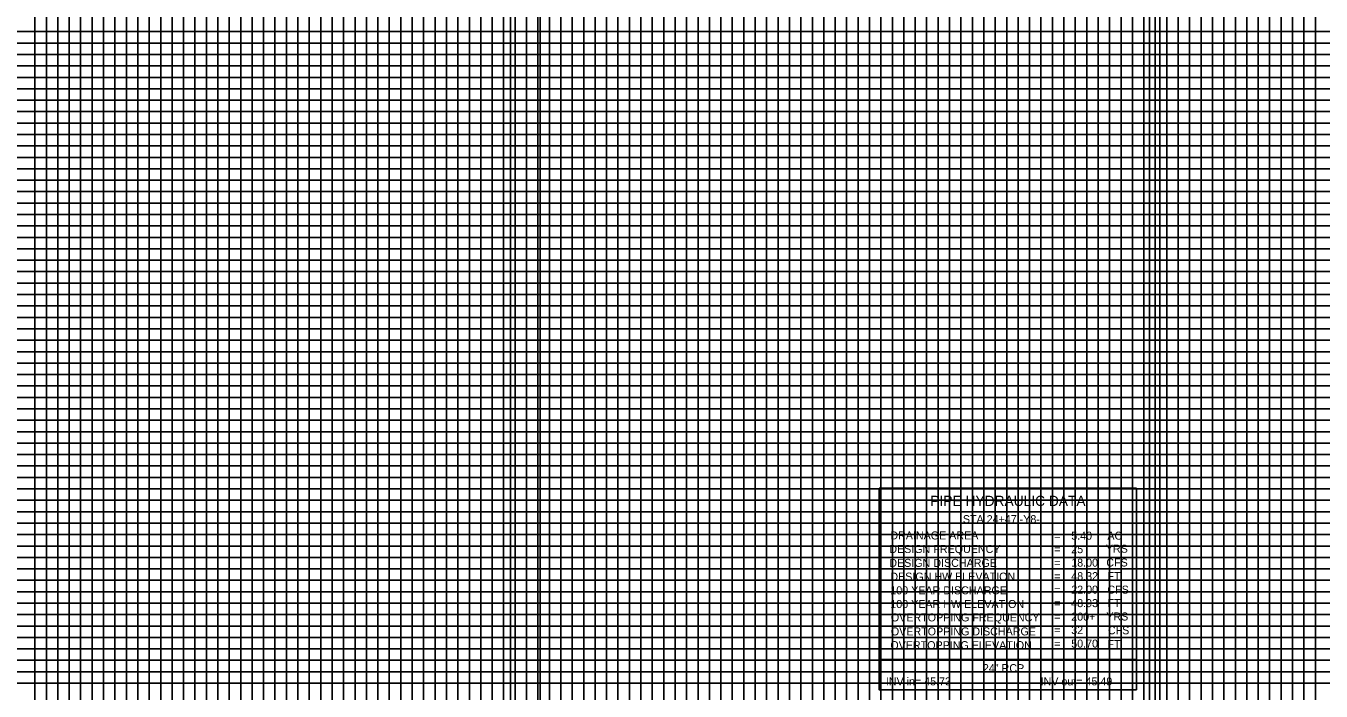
# Model space of a CAD drawing. Extents: x 2345490 to 2445302, y 465165 to 573888.
# Drawn here: x 2382738 to 2383304, y 541266 to 541557 of the extents above; entities that cross this region are included whole.
import ezdxf

# ---------------------------------------------------------------- set-up
doc = ezdxf.new("R2010")
doc.units = 0
for name, color, linetype in [('Old_Level_18', 7, 'Continuous'), ('Old_Level_4', 7, 'Continuous'), ('Old_Level_41', 7, 'Continuous'), ('Old_Level_42', 7, 'Continuous'), ('Old_Level_43', 7, 'Continuous'), ('Old_Level_50', 7, 'Continuous'), ('Old_Level_51', 7, 'Continuous')]:
    doc.layers.add(name, color=color, linetype=linetype)

msp = doc.modelspace()

# ---------------------------------------------------------------- linework, layer by layer
at = {"layer": 'Old_Level_18'}
for points in [[(2383216.79875, 542049.5045), (2381716.79875, 542049.5045), (2381716.79875, 540999.5045), (2383216.79875, 540999.5045)], [(2384616.79875, 542049.5045), (2383116.79875, 542049.5045), (2383116.79875, 540999.5045), (2384616.79875, 540999.5045)]]:
    msp.add_lwpolyline(points, close=True, dxfattribs=at)
at = {"layer": 'Old_Level_4'}
for p, q in [((2383111.01452, 541354.8205), (2383223.51452, 541354.8205)), ((2383111.01452, 541279.8205), (2383111.01452, 541354.8205)), ((2383223.51452, 541354.8205), (2383223.51452, 541279.8205)), ((2383223.51452, 541279.8205), (2383111.01452, 541279.8205))]:
    msp.add_line(p, q, dxfattribs=at)
msp.add_lwpolyline([(2383111.01452, 541279.8205), (2383223.51452, 541279.8205), (2383223.51452, 541266.6055), (2383111.01452, 541266.6055)], close=True, dxfattribs=at)
at = {"layer": 'Old_Level_41'}
for points in [[(2382691.79875, 542049.5045), (2382741.79875, 542049.5045), (2382741.79875, 541024.5045), (2382791.79875, 541024.5045), (2382791.79875, 542049.5045), (2382841.79875, 542049.5045), (2382841.79875, 541024.5045), (2382891.79875, 541024.5045), (2382891.79875, 542049.5045), (2382941.79875, 542049.5045), (2382941.79875, 541024.5045), (2382991.79875, 541024.5045), (2382991.79875, 542049.5045)], [(2382716.79875, 542049.5045), (2382766.79875, 542049.5045), (2382766.79875, 541024.5045), (2382816.79875, 541024.5045), (2382816.79875, 542049.5045), (2382866.79875, 542049.5045), (2382866.79875, 541024.5045), (2382916.79875, 541024.5045), (2382916.79875, 542049.5045), (2382966.79875, 542049.5045), (2382966.79875, 541024.5045), (2383016.79875, 541024.5045), (2383016.79875, 542049.5045), (2383043.09875, 542049.5045)], [(2383116.79875, 542049.5045), (2383166.79875, 542049.5045), (2383166.79875, 541024.5045), (2383216.79875, 541024.5045), (2383216.79875, 542049.5045), (2383266.79875, 542049.5045), (2383266.79875, 541024.5045), (2383316.79875, 541024.5045), (2383316.79875, 542049.5045), (2383366.79875, 542049.5045), (2383366.79875, 541024.5045), (2383416.79875, 541024.5045), (2383416.79875, 542049.5045), (2383466.79875, 542049.5045), (2383466.79875, 541024.5045), (2383516.79875, 541024.5045), (2383516.79875, 542049.5045), (2383566.79875, 542049.5045), (2383566.79875, 541024.5045), (2383616.79875, 541024.5045), (2383616.79875, 542049.5045), (2383666.79875, 542049.5045), (2383666.79875, 541024.5045), (2383716.79875, 541024.5045)], [(2383191.79875, 541024.5045), (2383191.79875, 542049.5045), (2383241.79875, 542049.5045), (2383241.79875, 541024.5045), (2383291.79875, 541024.5045), (2383291.79875, 542049.5045), (2383341.79875, 542049.5045), (2383341.79875, 541024.5045), (2383391.79875, 541024.5045), (2383391.79875, 542049.5045), (2383441.79875, 542049.5045), (2383441.79875, 541024.5045), (2383491.79875, 541024.5045), (2383491.79875, 542049.5045), (2383541.79875, 542049.5045), (2383541.79875, 541024.5045), (2383591.79875, 541024.5045), (2383591.79875, 542049.5045), (2383641.79875, 542049.5045), (2383641.79875, 541024.5045), (2383691.79875, 541024.5045), (2383691.79875, 542049.5045), (2383741.79875, 542049.5045)], [(2383041.79875, 541911.9545), (2383041.79875, 541024.5045), (2383091.79875, 541024.5045), (2383091.79875, 541911.9545)], [(2383141.79875, 541911.9545), (2383141.79875, 541024.5045)], [(2383216.79875, 541549.5045), (2381716.79875, 541549.5045), (2381716.79875, 541499.5045), (2383216.79875, 541499.5045)], [(2384616.79875, 541549.5045), (2383116.79875, 541549.5045), (2383116.79875, 541499.5045), (2384616.79875, 541499.5045)], [(2383216.79875, 541449.5045), (2381716.79875, 541449.5045), (2381716.79875, 541399.5045), (2383216.79875, 541399.5045)], [(2384616.79875, 541449.5045), (2383116.79875, 541449.5045), (2383116.79875, 541399.5045), (2384616.79875, 541399.5045)], [(2383216.79875, 541374.5045), (2381716.79875, 541374.5045), (2381716.79875, 541424.5045), (2383216.79875, 541424.5045)], [(2384616.79875, 541374.5045), (2383116.79875, 541374.5045), (2383116.79875, 541424.5045), (2384616.79875, 541424.5045)], [(2383216.79875, 541349.5045), (2381716.79875, 541349.5045), (2381716.79875, 541299.5045), (2383216.79875, 541299.5045)], [(2384616.79875, 541349.5045), (2383116.79875, 541349.5045), (2383116.79875, 541299.5045), (2384616.79875, 541299.5045)], [(2383216.79875, 541274.5045), (2381716.79875, 541274.5045), (2381716.79875, 541324.5045), (2383216.79875, 541324.5045)], [(2384616.79875, 541274.5045), (2383116.79875, 541274.5045), (2383116.79875, 541324.5045), (2384616.79875, 541324.5045)]]:
    msp.add_lwpolyline(points, dxfattribs=at)
at = {"layer": 'Old_Level_42'}
for points in [[(2383066.79875, 541911.9545), (2383066.79875, 541024.5045), (2383116.79875, 541024.5045), (2383116.79875, 541911.9545)], [(2383166.79875, 541911.9545), (2383166.79875, 541024.5045), (2383216.79875, 541024.5045)], [(2383216.79875, 541474.5045), (2381716.79875, 541474.5045), (2381716.79875, 541524.5045), (2383216.79875, 541524.5045)], [(2384616.79875, 541474.5045), (2383116.79875, 541474.5045), (2383116.79875, 541524.5045), (2384616.79875, 541524.5045)]]:
    msp.add_lwpolyline(points, dxfattribs=at)
at = {"layer": 'Old_Level_43'}
for points in [[(2382736.79875, 541024.5045), (2382746.79875, 541024.5045), (2382746.79875, 542049.5045), (2382751.79875, 542049.5045), (2382751.79875, 541024.5045), (2382756.79875, 541024.5045), (2382756.79875, 542049.5045), (2382761.79875, 542049.5045), (2382761.79875, 541024.5045), (2382771.79875, 541024.5045), (2382771.79875, 542049.5045), (2382776.79875, 542049.5045), (2382776.79875, 541024.5045), (2382781.79875, 541024.5045), (2382781.79875, 542049.5045), (2382786.79875, 542049.5045), (2382786.79875, 541024.5045)], [(2382786.79875, 541024.5045), (2382796.79875, 541024.5045), (2382796.79875, 542049.5045)], [(2382801.79875, 542049.5045), (2382801.79875, 541024.5045), (2382806.79875, 541024.5045), (2382806.79875, 542049.5045)], [(2382811.79875, 542049.5045), (2382811.79875, 541024.5045), (2382821.79875, 541024.5045), (2382821.79875, 542049.5045)], [(2382826.79875, 542049.5045), (2382826.79875, 541024.5045), (2382831.79875, 541024.5045), (2382831.79875, 542049.5045)], [(2382836.79875, 542049.5045), (2382836.79875, 541024.5045), (2382846.79875, 541024.5045), (2382846.79875, 542049.5045)], [(2382851.79875, 542049.5045), (2382851.79875, 541024.5045), (2382856.79875, 541024.5045), (2382856.79875, 542049.5045)], [(2382861.79875, 542049.5045), (2382861.79875, 541024.5045), (2382871.79875, 541024.5045), (2382871.79875, 542049.5045)], [(2382876.79875, 542049.5045), (2382876.79875, 541024.5045), (2382881.79875, 541024.5045), (2382881.79875, 542049.5045)], [(2382886.79875, 542049.5045), (2382886.79875, 541024.5045), (2382896.79875, 541024.5045), (2382896.79875, 542049.5045)], [(2382901.79875, 542049.5045), (2382901.79875, 541024.5045), (2382906.79875, 541024.5045), (2382906.79875, 542049.5045)], [(2382911.79875, 542049.5045), (2382911.79875, 541024.5045), (2382921.79875, 541024.5045), (2382921.79875, 542049.5045)], [(2382926.79875, 542049.5045), (2382926.79875, 541024.5045), (2382931.79875, 541024.5045), (2382931.79875, 542049.5045)], [(2382936.79875, 542049.5045), (2382936.79875, 541024.5045), (2382946.79875, 541024.5045), (2382946.79875, 542049.5045)], [(2382951.79875, 542049.5045), (2382951.79875, 541024.5045), (2382956.79875, 541024.5045), (2382956.79875, 542049.5045)], [(2382961.79875, 542049.5045), (2382961.79875, 541024.5045), (2382971.79875, 541024.5045), (2382971.79875, 542049.5045)], [(2382976.79875, 542049.5045), (2382976.79875, 541024.5045), (2382981.79875, 541024.5045), (2382981.79875, 542049.5045)], [(2382986.79875, 542049.5045), (2382986.79875, 541024.5045), (2382996.79875, 541024.5045), (2382996.79875, 542049.5045)], [(2383001.79875, 542049.5045), (2383001.79875, 541024.5045), (2383006.79875, 541024.5045), (2383006.79875, 542049.5045)], [(2383011.79875, 542049.5045), (2383011.79875, 541024.5045), (2383021.79875, 541024.5045), (2383021.79875, 541911.9545)], [(2383171.79875, 542049.5045), (2383171.79875, 541024.5045), (2383176.79875, 541024.5045), (2383176.79875, 542049.5045)], [(2383181.79875, 542049.5045), (2383181.79875, 541024.5045), (2383186.79875, 541024.5045), (2383186.79875, 542049.5045)], [(2383196.79875, 542049.5045), (2383196.79875, 541024.5045), (2383201.79875, 541024.5045), (2383201.79875, 542049.5045)], [(2383206.79875, 542049.5045), (2383206.79875, 541024.5045), (2383211.79875, 541024.5045), (2383211.79875, 542049.5045)], [(2383221.79875, 542049.5045), (2383221.79875, 541024.5045), (2383226.79875, 541024.5045), (2383226.79875, 542049.5045)], [(2383231.79875, 542049.5045), (2383231.79875, 541024.5045), (2383236.79875, 541024.5045), (2383236.79875, 542049.5045)], [(2383246.79875, 542049.5045), (2383246.79875, 541024.5045), (2383251.79875, 541024.5045), (2383251.79875, 542049.5045)], [(2383256.79875, 542049.5045), (2383256.79875, 541024.5045), (2383261.79875, 541024.5045), (2383261.79875, 542049.5045)], [(2383271.79875, 542049.5045), (2383271.79875, 541024.5045), (2383276.79875, 541024.5045), (2383276.79875, 542049.5045)], [(2383281.79875, 542049.5045), (2383281.79875, 541024.5045), (2383286.79875, 541024.5045), (2383286.79875, 542049.5045)], [(2383296.79875, 542049.5045), (2383296.79875, 541024.5045), (2383301.79875, 541024.5045), (2383301.79875, 542049.5045)], [(2383026.79875, 541911.9545), (2383026.79875, 541024.5045), (2383031.79875, 541024.5045), (2383031.79875, 541911.9545)], [(2383036.79875, 541911.9545), (2383036.79875, 541024.5045), (2383046.79875, 541024.5045), (2383046.79875, 541911.9545)], [(2383051.79875, 541911.9545), (2383051.79875, 541024.5045), (2383056.79875, 541024.5045), (2383056.79875, 541911.9545)], [(2383061.79875, 541911.9545), (2383061.79875, 541024.5045), (2383071.79875, 541024.5045), (2383071.79875, 541911.9545)], [(2383076.79875, 541911.9545), (2383076.79875, 541024.5045), (2383081.79875, 541024.5045), (2383081.79875, 541911.9545)], [(2383086.79875, 541911.9545), (2383086.79875, 541024.5045), (2383096.79875, 541024.5045), (2383096.79875, 541911.9545)], [(2383101.79875, 541911.9545), (2383101.79875, 541024.5045)], [(2383101.79875, 541024.5045), (2383106.79875, 541024.5045), (2383106.79875, 541911.9545)], [(2383111.79875, 541911.9545), (2383111.79875, 541024.5045), (2383121.79875, 541024.5045), (2383121.79875, 541911.9545)], [(2383126.79875, 541911.9545), (2383126.79875, 541024.5045), (2383131.79875, 541024.5045), (2383131.79875, 541911.9545)], [(2383136.79875, 541911.9545), (2383136.79875, 541024.5045), (2383146.79875, 541024.5045), (2383146.79875, 541911.9545)], [(2383151.79875, 541911.9545), (2383151.79875, 541024.5045), (2383156.79875, 541024.5045), (2383156.79875, 541911.9545)], [(2383161.79875, 541911.9545), (2383161.79875, 541024.5045), (2383171.79875, 541024.5045)], [(2383166.79875, 541554.5045), (2381766.79875, 541554.5045), (2381766.79875, 541544.5045), (2383166.79875, 541544.5045)], [(2384566.79875, 541554.5045), (2383166.79875, 541554.5045), (2383166.79875, 541544.5045), (2384566.79875, 541544.5045)], [(2383166.79875, 541539.5045), (2381766.79875, 541539.5045), (2381766.79875, 541534.5045), (2383166.79875, 541534.5045)], [(2384566.79875, 541539.5045), (2383166.79875, 541539.5045), (2383166.79875, 541534.5045), (2384566.79875, 541534.5045)], [(2383166.79875, 541529.5045), (2381766.79875, 541529.5045)], [(2384566.79875, 541529.5045), (2383166.79875, 541529.5045)], [(2381766.79875, 541519.5045), (2383166.79875, 541519.5045)], [(2383166.79875, 541519.5045), (2384566.79875, 541519.5045)], [(2383166.79875, 541514.5045), (2381766.79875, 541514.5045), (2381766.79875, 541509.5045), (2383166.79875, 541509.5045)], [(2384566.79875, 541514.5045), (2383166.79875, 541514.5045), (2383166.79875, 541509.5045), (2384566.79875, 541509.5045)], [(2383166.79875, 541504.5045), (2381766.79875, 541504.5045), (2381766.79875, 541494.5045), (2383166.79875, 541494.5045)], [(2384566.79875, 541504.5045), (2383166.79875, 541504.5045), (2383166.79875, 541494.5045), (2384566.79875, 541494.5045)], [(2383166.79875, 541489.5045), (2381766.79875, 541489.5045), (2381766.79875, 541484.5045), (2383166.79875, 541484.5045)], [(2384566.79875, 541489.5045), (2383166.79875, 541489.5045), (2383166.79875, 541484.5045), (2384566.79875, 541484.5045)], [(2383166.79875, 541479.5045), (2381766.79875, 541479.5045), (2381766.79875, 541469.5045), (2383166.79875, 541469.5045)], [(2384566.79875, 541479.5045), (2383166.79875, 541479.5045), (2383166.79875, 541469.5045), (2384566.79875, 541469.5045)], [(2383166.79875, 541464.5045), (2381766.79875, 541464.5045), (2381766.79875, 541459.5045), (2383166.79875, 541459.5045)], [(2384566.79875, 541464.5045), (2383166.79875, 541464.5045), (2383166.79875, 541459.5045), (2384566.79875, 541459.5045)], [(2383166.79875, 541454.5045), (2381766.79875, 541454.5045), (2381766.79875, 541444.5045), (2383166.79875, 541444.5045)], [(2384566.79875, 541454.5045), (2383166.79875, 541454.5045), (2383166.79875, 541444.5045), (2384566.79875, 541444.5045)], [(2383166.79875, 541439.5045), (2381766.79875, 541439.5045), (2381766.79875, 541434.5045), (2383166.79875, 541434.5045)], [(2384566.79875, 541439.5045), (2383166.79875, 541439.5045), (2383166.79875, 541434.5045), (2384566.79875, 541434.5045)], [(2383166.79875, 541429.5045), (2381766.79875, 541429.5045), (2381766.79875, 541419.5045), (2383166.79875, 541419.5045)], [(2384566.79875, 541429.5045), (2383166.79875, 541429.5045), (2383166.79875, 541419.5045), (2384566.79875, 541419.5045)], [(2383166.79875, 541414.5045), (2381766.79875, 541414.5045), (2381766.79875, 541409.5045), (2383166.79875, 541409.5045)], [(2384566.79875, 541414.5045), (2383166.79875, 541414.5045), (2383166.79875, 541409.5045), (2384566.79875, 541409.5045)], [(2383166.79875, 541404.5045), (2381766.79875, 541404.5045), (2381766.79875, 541394.5045), (2383166.79875, 541394.5045)], [(2384566.79875, 541404.5045), (2383166.79875, 541404.5045), (2383166.79875, 541394.5045), (2384566.79875, 541394.5045)], [(2383166.79875, 541389.5045), (2381766.79875, 541389.5045), (2381766.79875, 541384.5045), (2383166.79875, 541384.5045)], [(2384566.79875, 541389.5045), (2383166.79875, 541389.5045), (2383166.79875, 541384.5045), (2384566.79875, 541384.5045)], [(2383166.79875, 541379.5045), (2381766.79875, 541379.5045), (2381766.79875, 541369.5045), (2383166.79875, 541369.5045)], [(2384566.79875, 541379.5045), (2383166.79875, 541379.5045), (2383166.79875, 541369.5045), (2384566.79875, 541369.5045)], [(2383166.79875, 541364.5045), (2381766.79875, 541364.5045), (2381766.79875, 541359.5045), (2383166.79875, 541359.5045)], [(2384566.79875, 541364.5045), (2383166.79875, 541364.5045), (2383166.79875, 541359.5045), (2384566.79875, 541359.5045)], [(2383166.79875, 541354.5045), (2381766.79875, 541354.5045), (2381766.79875, 541344.5045), (2383166.79875, 541344.5045)], [(2384566.79875, 541354.5045), (2383166.79875, 541354.5045), (2383166.79875, 541344.5045), (2384566.79875, 541344.5045)], [(2383166.79875, 541339.5045), (2381766.79875, 541339.5045), (2381766.79875, 541334.5045), (2383166.79875, 541334.5045)], [(2384566.79875, 541339.5045), (2383166.79875, 541339.5045), (2383166.79875, 541334.5045), (2384566.79875, 541334.5045)], [(2383166.79875, 541329.5045), (2381766.79875, 541329.5045), (2381766.79875, 541319.5045), (2383166.79875, 541319.5045)], [(2384566.79875, 541329.5045), (2383166.79875, 541329.5045), (2383166.79875, 541319.5045), (2384566.79875, 541319.5045)], [(2383166.79875, 541314.5045), (2381766.79875, 541314.5045), (2381766.79875, 541309.5045), (2383166.79875, 541309.5045)], [(2384566.79875, 541314.5045), (2383166.79875, 541314.5045), (2383166.79875, 541309.5045), (2384566.79875, 541309.5045)], [(2383166.79875, 541304.5045), (2381766.79875, 541304.5045), (2381766.79875, 541294.5045), (2383166.79875, 541294.5045)], [(2384566.79875, 541304.5045), (2383166.79875, 541304.5045), (2383166.79875, 541294.5045), (2384566.79875, 541294.5045)], [(2383166.79875, 541289.5045), (2381766.79875, 541289.5045), (2381766.79875, 541284.5045), (2383166.79875, 541284.5045)], [(2384566.79875, 541289.5045), (2383166.79875, 541289.5045), (2383166.79875, 541284.5045), (2384566.79875, 541284.5045)], [(2383166.79875, 541279.5045), (2381766.79875, 541279.5045), (2381766.79875, 541269.5045), (2383166.79875, 541269.5045)], [(2384566.79875, 541279.5045), (2383166.79875, 541279.5045), (2383166.79875, 541269.5045), (2384566.79875, 541269.5045)]]:
    msp.add_lwpolyline(points, dxfattribs=at)
at = {"layer": 'Old_Level_50'}
for points in [[(2383229.29875, 542052.0545), (2381562.79875, 542052.0545), (2381562.79875, 540996.9545), (2383229.29875, 540996.9545)], [(2384629.29875, 542052.0545), (2382962.79875, 542052.0545), (2382962.79875, 540996.9545), (2384629.29875, 540996.9545)]]:
    msp.add_lwpolyline(points, close=True, dxfattribs=at)
at = {"layer": 'Old_Level_51'}
for points in [[(2383233.79875, 542074.5045), (2381549.79875, 542074.5045), (2381549.79875, 540974.5045), (2383233.79875, 540974.5045)], [(2384633.79875, 542074.5045), (2382949.79875, 542074.5045), (2382949.79875, 540974.5045), (2384633.79875, 540974.5045)]]:
    msp.add_lwpolyline(points, close=True, dxfattribs=at)

# ---------------------------------------------------------------- texts
at = {"layer": 'Old_Level_4'}
for s, height, p in [('PIPE HYDRAULIC DATA', 4.49985, (2383133.41452, 541346.9955)), ('STA 24+47 -Y8-', 3.4998, (2383147.63527, 541339.495)), ('DRAINAGE AREA', 3.49995, (2383115.91452, 541332.3705)), ('=        ', 3.49995, (2383187.56452, 541332.2705)), ('5.40', 3.49995, (2383195.02502, 541332.27005)), ('AC', 3.49995, (2383210.83952, 541332.2705)), ('DESIGN FREQUENCY', 3.49995, (2383115.46452, 541326.4455)), ('=        ', 3.49995, (2383187.56452, 541326.3705)), ('25', 3.49995, (2383195.02502, 541326.3701)), ('YRS', 3.49995, (2383210.13952, 541326.5705)), ('DESIGN DISCHARGE', 3.49995, (2383115.46452, 541320.3705)), ('=        ', 3.49995, (2383187.56452, 541320.4705)), ('18.00', 3.49995, (2383195.02502, 541320.47015)), ('CFS', 3.49995, (2383210.36452, 541320.5455)), ('DESIGN HW ELEVATION', 3.49995, (2383115.91452, 541314.3705)), ('=        ', 3.49995, (2383187.56452, 541314.5705)), ('48.32', 3.49995, (2383195.02502, 541314.5702)), ('FT', 3.49995, (2383210.83952, 541314.5705)), ('100 YEAR DISCHARGE', 3.49995, (2383115.91452, 541308.3705)), ('=        ', 3.49995, (2383187.56452, 541308.6705)), ('22.00', 3.49995, (2383195.02502, 541308.67025)), ('CFS', 3.49995, (2383210.83952, 541308.6705)), ('100 YEAR HW ELEVATION', 3.49995, (2383115.91452, 541302.3705)), ('=        ', 3.49995, (2383187.56452, 541302.7705)), ('48.93', 3.49995, (2383195.02502, 541302.7703)), ('FT', 3.49995, (2383210.83952, 541302.7705)), ('OVERTOPPING FREQUENCY', 3.49995, (2383116.13952, 541296.5205)), ('200+', 3.49995, (2383195.02502, 541296.87035)), ('YRS', 3.49995, (2383210.36452, 541296.9205)), ('OVERTOPPING DISCHARGE', 3.49995, (2383116.13952, 541290.3955)), ('=        ', 3.49995, (2383187.56452, 541296.8705)), ('32', 3.49995, (2383195.02502, 541290.9704)), ('CFS', 3.49995, (2383211.06452, 541290.8955)), ('=        ', 3.49995, (2383187.56452, 541290.9705)), ('50.70', 3.49995, (2383195.02502, 541285.07045)), ('FT', 3.49995, (2383210.83952, 541284.8705)), ('OVERTOPPING ELEVATION', 3.49995, (2383115.91452, 541284.3705)), ('=        ', 3.49995, (2383187.56452, 541285.0705)), ('24" RCP', 3.4998, (2383156.40377, 541274.32325)), ('INV in= 45.73', 3.4998, (2383113.94702, 541268.5325)), ('INV out= 45.49', 3.4998, (2383181.62377, 541268.5325))]:
    msp.add_text(s, height=height, dxfattribs=at).set_placement(p)

doc.saveas('drawing.dxf')
